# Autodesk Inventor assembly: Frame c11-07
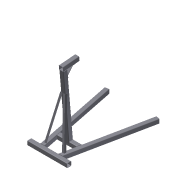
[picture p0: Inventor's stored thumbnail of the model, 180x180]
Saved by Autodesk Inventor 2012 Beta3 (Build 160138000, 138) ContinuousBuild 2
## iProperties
Created: 2011-01
Part Number: Frame c11-07
Document SubType Name: Assembly
Designer: Beta-8540w
_FrameDoc: Frame Assembly
_Version: 15.0.0
Author: Beta-8540w
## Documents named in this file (20)
- C:\Inventor 2012 Essentials\Assemblies\Chapter 11\Frame\Frame c11-07.iam
- C:\Inventor 2012 Essentials\Assemblies\Chapter 11\Frame\Skeleton-c11-07.ipt
- C:\Inventor 2012 Essentials\Assemblies\Chapter 11\Frame\ANSI L 1.5 x 1.5 x 3_16 00000003.ipt
- ANSI L 1.5 x 1.5 x 3_16 00000003.ipt
- C:\Inventor 2012 Essentials\Assemblies\Chapter 11\Frame\ANSI L 1.5 x 1.5 x 3_16 00000004.ipt
- ANSI L 1.5 x 1.5 x 3_16 00000004.ipt
- C:\Inventor 2012 Essentials\Assemblies\Chapter 11\Frame\ANSI 2 1_4x5_16 00000005.ipt
- ANSI 2 1_4x5_16 00000005.ipt
- C:\Inventor 2012 Essentials\Assemblies\Chapter 11\Frame\ANSI 3x3x3_16 00000030.ipt
- ANSI 3x3x3_16 00000030.ipt
- C:\Inventor 2012 Essentials\Assemblies\Chapter 11\Frame\ANSI 3x3x3_16 00000032.ipt
- ANSI 3x3x3_16 00000032.ipt
- C:\Inventor 2012 Essentials\Assemblies\Chapter 11\Frame\ANSI 3x3x3_16 00000033.ipt
- ANSI 3x3x3_16 00000033.ipt
- C:\Inventor 2012 Essentials\Assemblies\Chapter 11\Frame\ANSI 3x3x3_16 00000034.ipt
- ANSI 3x3x3_16 00000034.ipt
- C:\Inventor 2012 Essentials\Assemblies\Chapter 11\Frame\ANSI 3x3x3_16 00000035.ipt
- ANSI 3x3x3_16 00000035.ipt
- C:\Inventor 2012 Essentials\Assemblies\Chapter 11\Frame\ANSI 3x3x3_16 00000036.ipt
- ANSI 3x3x3_16 00000036.ipt
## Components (10 placed, 10 different names)
1. Frame Reference Model
2. ANSI L 1.5 x 1.5 x 3_16 00000003:1
3. ANSI L 1.5 x 1.5 x 3_16 00000004:1
4. ANSI 2 1_4x5_16 00000005:1
5. ANSI 3x3x3_16 00000030:1
6. ANSI 3x3x3_16 00000032:1
7. ANSI 3x3x3_16 00000033:1
8. ANSI 3x3x3_16 00000034:1
9. ANSI 3x3x3_16 00000035:1
10. ANSI 3x3x3_16 00000036:1
